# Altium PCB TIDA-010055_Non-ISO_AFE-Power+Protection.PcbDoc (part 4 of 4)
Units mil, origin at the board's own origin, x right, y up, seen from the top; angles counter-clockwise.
Board outline 3622.05 x 4330.71 mil, 4 copper layers (Top Layer, GND Layer, PWR Layer, Bottom Layer), stack 63.6 mil thick; 398 components, 177 nets, 1104 pads, 428 vias.
Unrouted connection lines stored in the file: 1.
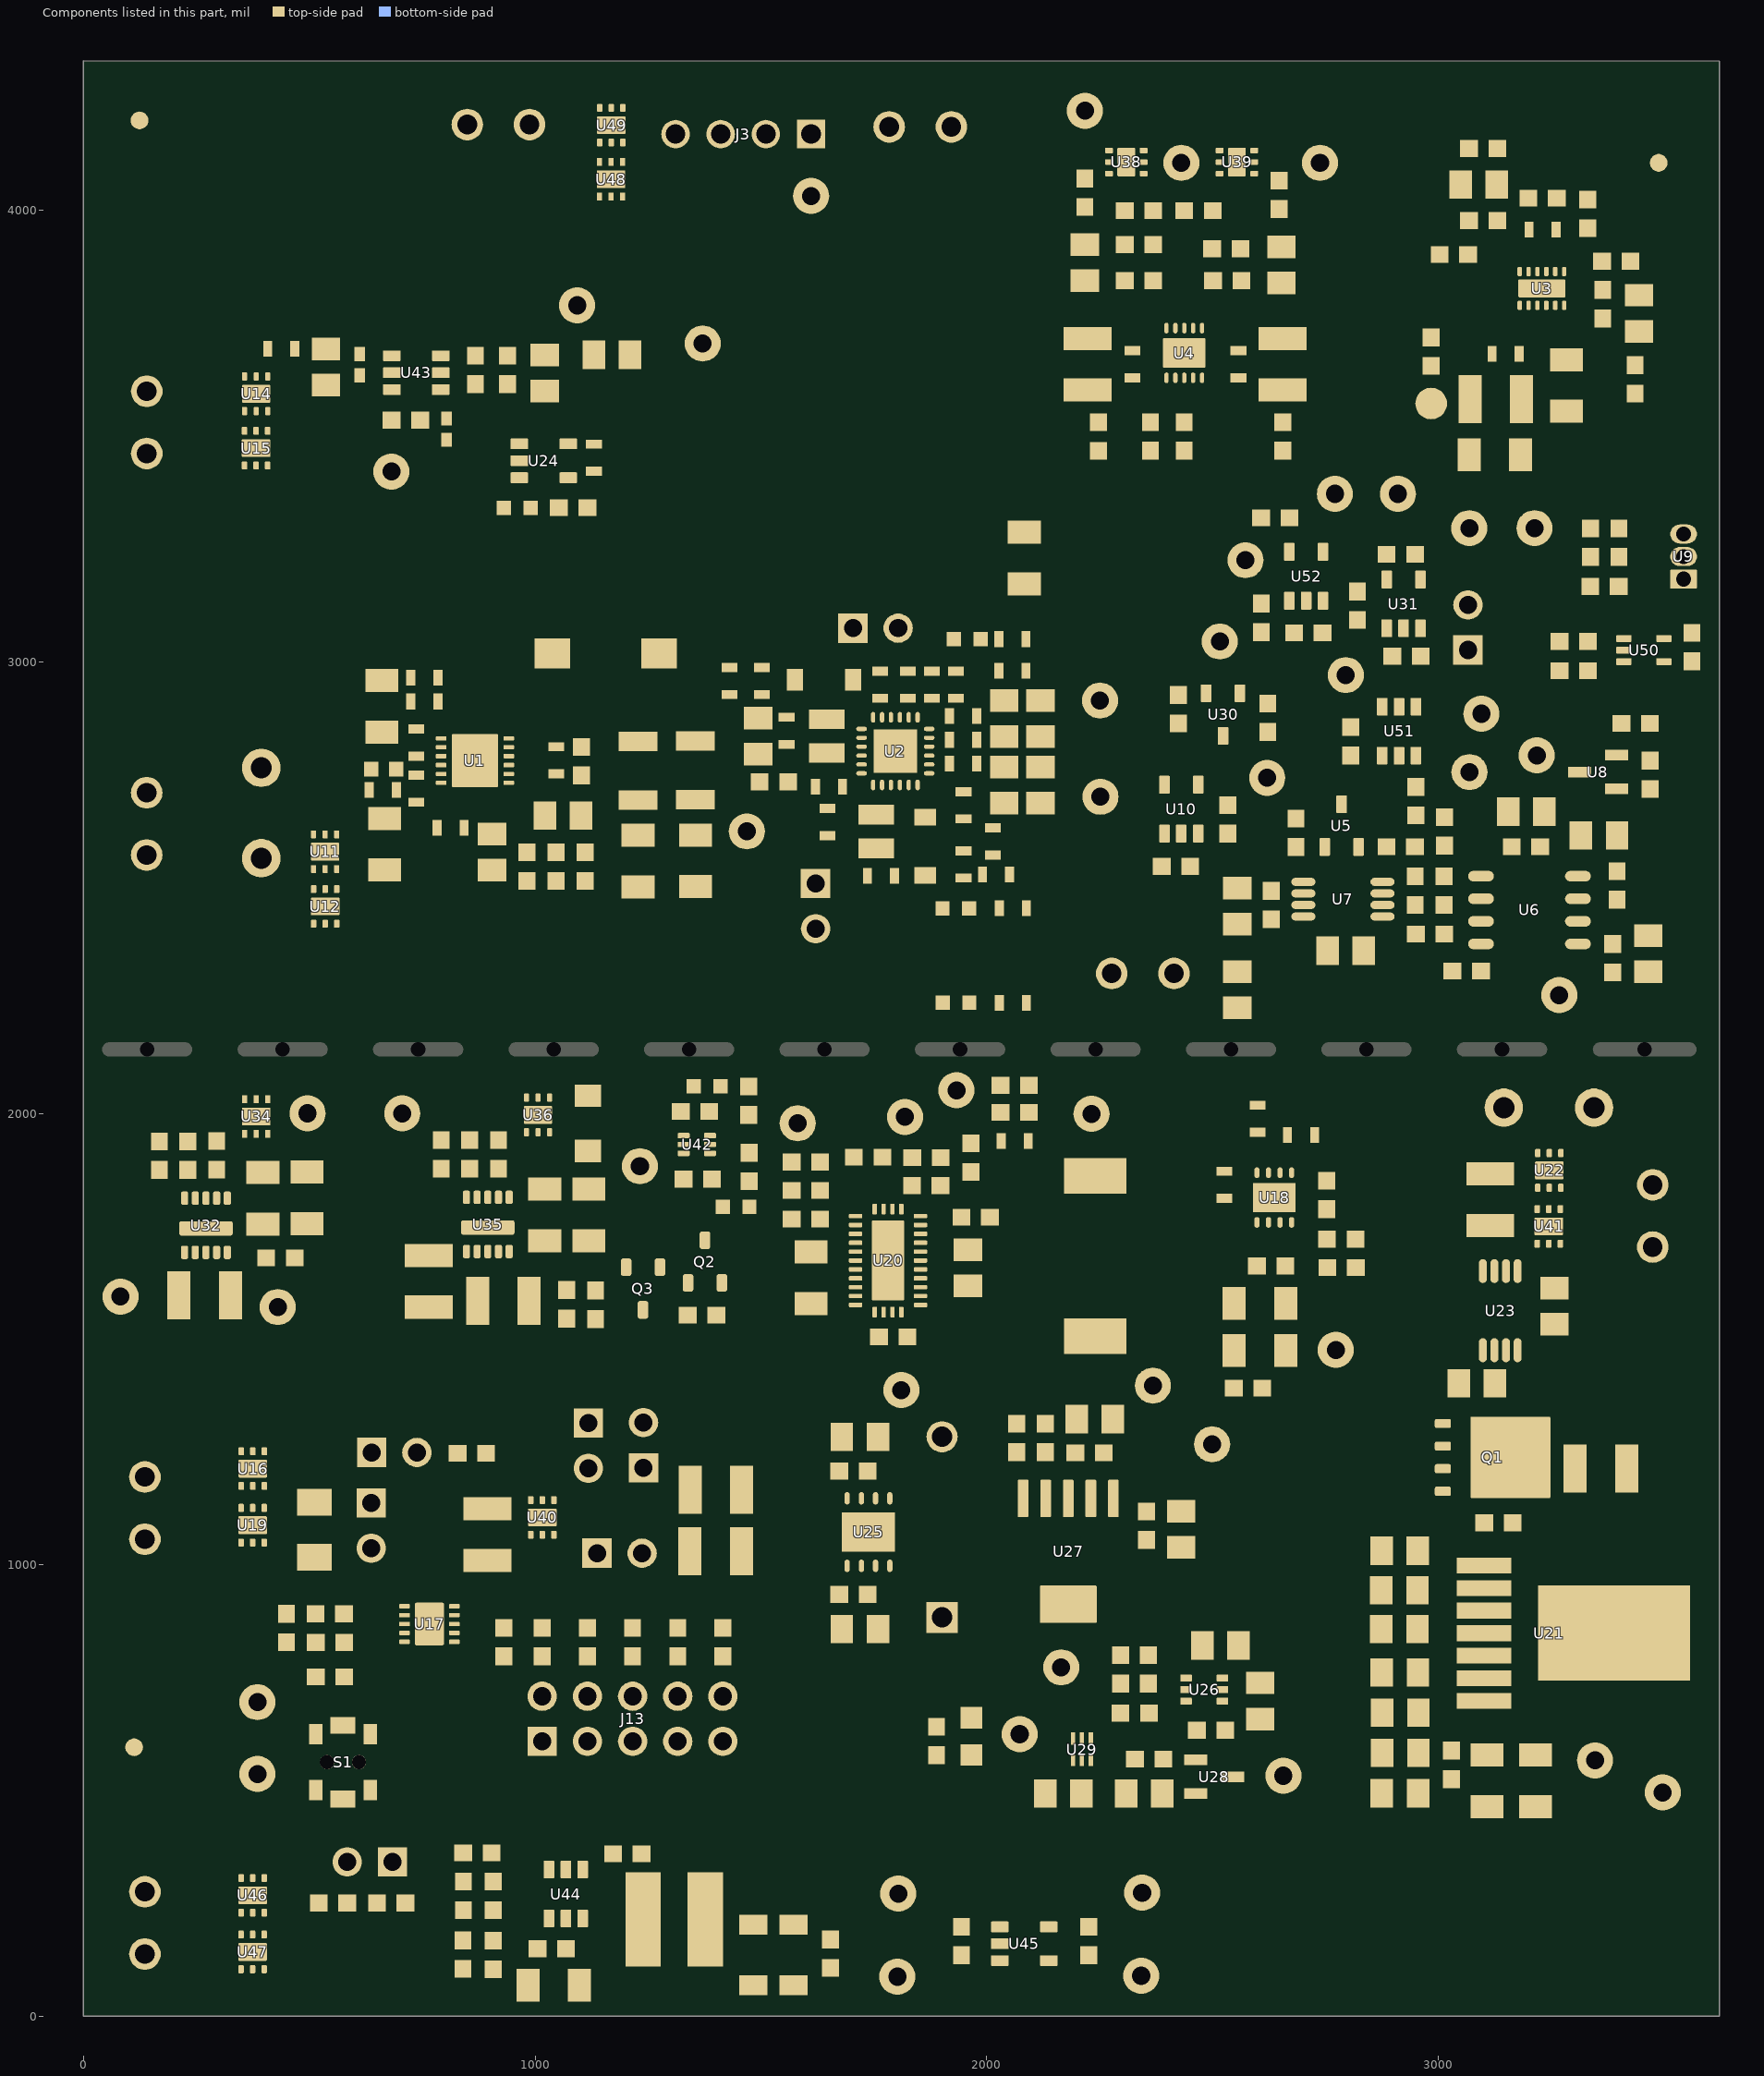
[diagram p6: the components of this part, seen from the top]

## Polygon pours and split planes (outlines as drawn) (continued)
NetU11_1 on Bottom Layer "Top Layer-No Net" (solid, pour order 84): 562.66,2588.76 504.66,2588.76 501.66,2585.76 501.66,2440.76 503.66,2438.76 564.66,2438.76 567.66,2441.76 567.66,2584.76 563.66,2588.76
NetU14_1 on Bottom Layer "Top Layer-No Net" (solid, pour order 90): 409.61,3603.56 351.61,3603.56 348.61,3600.56 348.61,3455.56 350.61,3453.56 411.61,3453.56 414.61,3456.56 414.61,3599.56 410.61,3603.56
NetJ4_1 on Bottom Layer "Top Layer-No Net" (solid, pour order 118): 127.88,2672.16 364.88,2672.16 434.88,2742.16 438.88,2746.16 438.88,2783.16 438.88,2786.16 413.88,2811.16 373.88,2811.16 354.88,2792.16 309.88,2747.16 140.88,2747.16 112.88,2747.16 100.88,2735.16 100.88,2686.16 114.88,2672.16
3.3V_1 on Bottom Layer "Top Layer-No Net" (solid, pour order 234): 23 vertices, not listed, extent 1677,1028 1939,1433
GND1 on Bottom Layer "Top Layer-No Net" (solid, pour order 252): 32 vertices, not listed, extent 38,1532 544,2047
24V/12V_IN on Bottom Layer "Top Layer-No Net" (solid, pour order 270): 3328.12,2084.89 3362.12,2084.89 3522.12,1924.89 3522.12,1839.89 3522.12,1824.89 3505.12,1807.89 3444.12,1807.89 3433.12,1818.89 3433.12,1883.89 3301.12,2015.89 3295.12,2021.89 3295.12,2051.89
-12V on Bottom Layer "net" (solid, remove dead copper, pour order 388): 2705,4161 2534,4161 2529,4156 2529,4054.67 2538.67,4045 2859.8,4045 3286,4045 3368,3963 3368,3526 3382,3512 3533,3512 3552,3531 3552,3626 3552,4018 3409,4161
+3.3V on Bottom Layer "net" (solid, remove dead copper, pour order 392): 2519,3009 2906,3396 3085,3396 3565,3396 3599,3362 3599,2251 3547,2199 3537.72,2189.72 2532.28,2189.72 2519,2203
NetC123_1 on Bottom Layer "vd" (solid, remove dead copper, pour order 534): 17 vertices, not listed, extent 437,31.57 1177.07,289
GND_S on Bottom Layer "net" (solid, remove dead copper, pour order 542): 73,388 3556,388 3577,367 3586,358 3590,354 3590,307 3590,53 3568,31 69,31 44,56 26,74 26,368 46,388
+5V_IN on Top Layer "vdd" (solid, remove dead copper, pour order 582): 1182,3824 1189,3831 1416,3831 1436,3811 1436,3651 1421,3636 1190,3636 1182,3644
EXT_5V on Top Layer "vdd" (solid, remove dead copper, pour order 580): 1061.26,3647.06 1051.32,3657 781.08,3657 768.28,3669.8 768.28,3816.28 782,3830 1148.89,3830 1156.89,3822 1156.89,3657.04 1146.92,3647.06
NetJ1_1 on Top Layer "vdd" (solid, remove dead copper, pour order 578): 436.52,3632 436.52,3724.48 429,3732 103.2,3732 77.49,3706.29 77.49,3581.4 95.64,3563.25 199.22,3563.25 258.97,3623 427.53,3623
GND on Top Layer "vdd" (solid, remove dead copper, pour order 576): 429.23,3441.58 272.5,3441.58 215.08,3499 91.49,3499 77.49,3485 77.49,3335.89 94.38,3319 458,3319 470,3331 470,3438 466,3442
GND on Top Layer "vdd" (solid, remove dead copper, pour order 572): 2273.09,3217.43 48.88,3217.43 -0.12,3168.43 -0.12,2268.43 77.31,2191 2284.11,2191 2310,2216.89 2310,3180.53
GND on Top Layer "Top Layer-No Net" (solid, pour order 570): 33 vertices, not listed, extent 103.01,2351.16 1505.88,3057.83
NetC1_1 on Top Layer "vdd" (solid, remove dead copper, pour order 568): 1182.88,3043.43 1195.88,3056.43 1345.88,3056.43 1360.88,3041.43 1360.88,2899.68 1410.41,2850.16 1410.41,2797.96 1398.88,2786.43 1192.2,2786.43 1182.88,2795.76
NetC2_2 on Top Layer "vdd" (solid, remove dead copper, pour order 562): 935.64,2799.72 927.88,2807.47 927.88,3045.83 939.88,3057.83 1119.78,3057.83 1131.88,3045.73 1131.88,2798.43 1123.88,2790.43 1076.17,2790.43 1066.88,2799.72
VIN on Top Layer "vd" (solid, remove dead copper, pour order 558): 20 vertices, not listed, extent 773,3947.71 1544.98,4260
AGND on Top Layer "vd" (solid, remove dead copper, pour order 556): 33 vertices, not listed, extent 947.98,4121.71 1978.98,4297.71
GND1 on Top Layer "vd" (solid, remove dead copper, pour order 518): 19 vertices, not listed, extent 896,1805 1271,1962.28
DCDC_-10P5V on Top Layer "vd" (solid, remove dead copper, pour order 516): 36 vertices, not listed, extent 662.09,1668.86 1161.09,2064.48
+24V_IN1 on Top Layer "vd" (solid, remove dead copper, pour order 510): 24 vertices, not listed, extent 266,1279 1156,1710
GND1 on Top Layer "vd" (solid, remove dead copper, pour order 506): 1019.75,1633.94 962.75,1633.94 952.75,1623.94 952.75,1490.94 958.75,1484.94 1020.75,1484.94 1026.75,1490.94 1026.75,1627.94 1020.75,1633.94
GND1 on Top Layer "net" (solid, remove dead copper, pour order 504): 36 vertices, not listed, extent 3000,430 3561,1768
VIN1 on Top Layer "net" (solid, remove dead copper, pour order 502): 22 vertices, not listed, extent 93.12,1103 683.12,1344
NetC127_2 on Top Layer "net" (solid, remove dead copper, pour order 484): 23 vertices, not listed, extent 1092.07,74.98 1283.07,381.98
GND_S on Top Layer "net" (solid, remove dead copper, pour order 482): 36 vertices, not listed, extent 67,31.6 1388,384
NetC123_1 on Top Layer "net" (solid, remove dead copper, pour order 478): 1058.07,184.98 1045.07,171.98 1045.07,38.57 1052.07,31.57 1173.67,31.57 1177.07,34.98 1177.07,166.98 1166.07,177.98 1088.07,177.98 1078.07,187.98 1078.07,238.41 1058.07,238.41
NetU46_1 on Top Layer "Top Layer-No Net" (solid, pour order 474): 401.9,281.42 343.9,281.42 340.9,278.42 340.9,133.42 342.9,131.42 403.9,131.42 406.9,134.42 406.9,277.42 402.9,281.42
NetC60_1 on Top Layer "net" (solid, remove dead copper, pour order 472): 459.99,3666.25 706.81,3666.25 711.81,3671.25 711.81,3718.25 703.81,3726.25 699.81,3730.25 558.81,3730.25 462.99,3730.25 454.99,3722.25 454.99,3671.25
NetC78_1 on Top Layer "net" (solid, remove dead copper, pour order 430): 43 vertices, not listed, extent 2892,1196 3287,2061
NetC79_1 on Top Layer "net" (solid, remove dead copper, pour order 424): 25 vertices, not listed, extent 3011,975 3325,1506
VDC_5V_1 on Top Layer "net" (solid, remove dead copper, pour order 410): 21 vertices, not listed, extent 1915,1741.35 2556.12,2091
-12V on Top Layer "net" (solid, remove dead copper, pour order 370): 2795,4055 2795,4150 2784,4161 2548,4161 2540,4153 2540,4054 2549,4045 2785,4045
+24V_IN on Top Layer "net" (solid, remove dead copper, pour order 368): 23 vertices, not listed, extent 1192,1281 1728,1790.89
NetC68_1 on Top Layer "net" (solid, remove dead copper, pour order 366): 17 vertices, not listed, extent 1201,967 1372,1235
GND1 on Top Layer "dg" (solid, remove dead copper, pour order 364): 783,1195 783,1106 793,1096 967,1096 980,1083 1049,1083 1061,1095 1061,1183 1043,1201 789,1201
VOUT1 on Top Layer "dg" (solid, remove dead copper, pour order 362): 30 vertices, not listed, extent 812,901 1276,1250
NetJ17_2 on Top Layer "dg" (solid, remove dead copper, pour order 358): 603,1063 603,963 627,939 665,901 705,901 711,901 711,1059 699,1071 611,1071
GND1 on Top Layer "dg" (solid, remove dead copper, pour order 354): 17 vertices, not listed, extent 93.12,821 566,1100.89
NetC75_2 on Top Layer "Top Layer-No Net" (solid, pour order 198): 18 vertices, not listed, extent 1836.12,1465 2377.12,1660.89
GND1 on Top Layer "Top Layer-No Net" (solid, pour order 172): 42 vertices, not listed, extent 1573.12,1500.89 2051.12,2091
NetC32_2 on Top Layer "Top Layer-No Net" (solid, pour order 66): 2282.4,3643.91 2268.4,3629.91 2258.4,3629.91 2160.4,3629.91 2156.4,3625.91 2156.4,3517.91 2164.4,3509.91 2268.4,3509.91 2292.4,3533.91 2375.4,3616.91 2375.4,3633.91 2375.4,3639.91 2371.4,3643.91
NetC36_1 on Top Layer "Top Layer-No Net" (solid, pour order 64): 22 vertices, not listed, extent 2167.4,3754.91 2367.4,4028.91
NetC40_2 on Top Layer "Top Layer-No Net" (solid, pour order 62): 2464.4,3945.91 2478.4,3959.91 2478.4,4008.91 2478.4,4017.91 2481.4,4020.91 2520.4,4020.91 2523.4,4017.91 2523.4,3824.91 2482.4,3783.91 2472.4,3783.91 2464.4,3791.91
NetC40_1 on Top Layer "Top Layer-No Net" (solid, pour order 60): 21 vertices, not listed, extent 2503.4,3763.91 2706.4,4023.91
AGND on Top Layer "Top Layer-No Net" (solid, pour order 58): 33 vertices, not listed, extent 2167.4,3654.47 2718.4,3868.91
NetC43_2 on Top Layer "Top Layer-No Net" (solid, pour order 56): 2592.4,3643.91 2606.4,3629.91 2616.4,3629.91 2714.4,3629.91 2718.4,3625.91 2718.4,3517.91 2710.4,3509.91 2606.4,3509.91 2582.4,3533.91 2499.4,3616.91 2499.4,3633.91 2499.4,3639.91 2503.4,3643.91
NetC36_2 on Top Layer "TOP_LAYER_NETC36_2_P050" (solid, remove dead copper, pour order 50): 2347.4,4009 2347.4,4014 2352.4,4019 2388.32,4019 2392.4,4014.91 2392.4,3975 2407.4,3960 2407.4,3769.47 cw(c2401.99,3778.65) 2402.4,3768 2397.4,3769 2347.4,3819
AGND on Top Layer "TOP_LAYER_AGND_P036" (solid, remove dead copper, pour order 36): 30 vertices, not listed, extent 3044.2,3525.5 3279.2,3936.98
NetU14_1 on Top Layer "Top Layer-No Net" (solid, pour order 30): 409.61,3603.56 351.61,3603.56 348.61,3600.56 348.61,3455.56 350.61,3453.56 411.61,3453.56 414.61,3456.56 414.61,3599.56 410.61,3603.56
NetU11_1 on Top Layer "Top Layer-No Net" (solid, pour order 26): 562.66,2588.76 504.66,2588.76 501.66,2585.76 501.66,2440.76 503.66,2438.76 564.66,2438.76 567.66,2441.76 567.66,2584.76 563.66,2588.76
NetC39_1 on Top Layer "Top Layer-No Net" (solid, pour order 68): 18 vertices, not listed, extent 3296.29,3637.23 3477.83,3795.23
NetC34_1 on Top Layer "Top Layer-No Net" (solid, pour order 70): 19 vertices, not listed, extent 3103.83,3891.23 3192.83,4161.23
NetC9_2 on Top Layer "Top Layer-No Net" (solid, pour order 72): 3155.83,3483.23 3155.83,3707.23 3172.83,3724.23 3194.83,3724.23 3206.83,3736.23 3214.83,3744.23 3214.83,3779.23 3214.83,3797.23 3224.83,3797.23 3224.83,3720.23 3211.83,3707.23 3211.83,3425.23 3206.83,3420.23 3160.83,3420.23 3155.83,3425.23
NetPT1_2 on Top Layer "Top Layer-No Net" (solid, pour order 74): 22 vertices, not listed, extent 342.88,2520.16 649.88,2734.16
NetJ4_1 on Top Layer "Top Layer-No Net" (solid, pour order 100): 127.88,2672.16 364.88,2672.16 434.88,2742.16 438.88,2746.16 438.88,2783.16 438.88,2786.16 413.88,2811.16 373.88,2811.16 354.88,2792.16 309.88,2747.16 140.88,2747.16 112.88,2747.16 100.88,2735.16 100.88,2686.16 114.88,2672.16
+3.3V on Top Layer "Top Layer-No Net" (solid, pour order 120): 19 vertices, not listed, extent 2455,2476.72 2764,2645.72
+5V_IN on Top Layer "Top Layer-No Net" (solid, pour order 140): 3093.98,3415.23 2990.98,3415.23 2984.98,3421.23 2984.98,3495.23 2989.98,3500.23 3092.98,3500.23 3097.98,3495.23 3097.98,3419.23
NetU16_1 on Top Layer "Top Layer-No Net" (solid, pour order 142): 402.04,1226.43 344.04,1226.43 341.04,1223.43 341.04,1078.43 343.04,1076.43 404.04,1076.43 407.04,1079.43 407.04,1222.43 403.04,1226.43
NetU22_1 on Top Layer "Top Layer-No Net" (solid, pour order 168): 3273.46,1890.75 3215.46,1890.75 3212.46,1887.75 3212.46,1742.75 3214.46,1740.75 3275.46,1740.75 3278.46,1743.75 3278.46,1886.75 3274.46,1890.75
NetC67_2 on Top Layer "g" (solid, remove dead copper, pour order 170): 39 vertices, not listed, extent 550.84,463.29 1545.84,1056.66
24V/12V_IN on Top Layer "Top Layer-No Net" (solid, pour order 200): 3328.12,2084.89 3362.12,2084.89 3522.12,1924.89 3522.12,1839.89 3522.12,1824.89 3505.12,1807.89 3444.12,1807.89 3433.12,1818.89 3433.12,1883.89 3301.12,2015.89 3295.12,2021.89 3295.12,2051.89
NetR65_1 on Top Layer "Top Layer-No Net" (solid, pour order 214): 2927.12,977.89 2979.12,977.89 2983.12,973.89 2983.12,824.89 2979.12,820.89 2931.12,820.89 2927.12,824.89
VDC_5V on Top Layer "Top Layer-No Net" (solid, pour order 218): 18 vertices, not listed, extent 2266,1097.1 2574,1626
GND1 on Top Layer "Top Layer-No Net" (solid, pour order 224): 30 vertices, not listed, extent 2051.6,871 2465,1401
3.3V_2 on Top Layer "Top Layer-No Net" (solid, pour order 226): 2414.12,1209 2257.89,1208.89 2248,1199 2248,1108.14 2240.03,1100.17 2219.83,1100.17 2212,1108 2212,1193 2240.03,1221.03 2240.03,1413.03 2270,1443 2411,1443 2418,1436 2418,1212.88
3.3V_1 on Top Layer "Top Layer-No Net" (solid, pour order 228): 23 vertices, not listed, extent 1677,1028 1939,1433
VDC_5V on Top Layer "Top Layer-No Net" (solid, pour order 232): 1714,1009 1714,914 1731,897 1731,819 1738,812 1932,812 1945,825 1945,915 1935,925 1858,925 1845,938 1845,1004 1836,1013 1718,1013
GND1 on Top Layer "Top Layer-No Net" (solid, pour order 236): 23 vertices, not listed, extent 1584,811 1706,1331
GND1 on Top Layer "Top Layer-No Net" (solid, pour order 238): 32 vertices, not listed, extent 38,1532 544,2047
DCDC_+10P5V on Top Layer "Top Layer-No Net" (solid, pour order 250): 28 vertices, not listed, extent 273,1797 544,2082
AGND on Top Layer "net" (solid, remove dead copper, pour order 380): 2290,4157 2299,4166 2503,4166 2524,4145 2524,4072.87 2501.13,4050 2307,4050 2290,4067
+12V on Top Layer "net" (solid, remove dead copper, pour order 382): 20 vertices, not listed, extent 2167.4,4050 3088,4277
+14V on Top Layer "net" (solid, remove dead copper, pour order 384): 2217,3489 2213,3485 2213,3417 2219,3411 2383,3411 2389,3417 2389,3486 2386,3489
GND1 on Top Layer "vd" (solid, remove dead copper, pour order 526): 29 vertices, not listed, extent 2588,1752 2785,1980.54
VDC_5V_2 on Top Layer "vd" (solid, remove dead copper, pour order 528): 17 vertices, not listed, extent 3004,523 3396,716
NetC123_1 on Top Layer "vd" (solid, remove dead copper, pour order 532): 20 vertices, not listed, extent 69,212 544,388
5V_S on Top Layer "vd" (solid, remove dead copper, pour order 536): 19 vertices, not listed, extent 1331.07,102.98 2051.55,348.98
GND_S on Top Layer "vd" (solid, remove dead copper, pour order 538): 19 vertices, not listed, extent 1415,31.6 2401,156
3V3_S on Top Layer "vd" (solid, remove dead copper, pour order 540): 2116,195 2116,335 2125,344 2392,344 2401,335 2401,198 2388,185 2381,178 2230,178 2119,178 2116,181
NetU48_1 on Top Layer "vd" (solid, remove dead copper, pour order 546): 1209.6,4054.71 1209.6,4193.09 1201.98,4200.71 1130.98,4200.71 1123.98,4193.71 1123.98,4055.71 1130.98,4048.71 1203.6,4048.71 1209.6,4054.71
+5V_IN on Top Layer "vd" (solid, remove dead copper, pour order 560): 21 vertices, not listed, extent 2418,2282 2636,2644.72
GND_S on GND Layer "net" (solid, remove dead copper, pour order 488): 73,388 3556,388 3577,367 3586,358 3590,354 3590,307 3590,53 3568,31 69,31 44,56 26,74 26,368 46,388
GND1 on GND Layer "Top Layer-No Net" (solid, remove dead copper, pour order 298): 834,2091 3555,2091 3591,2055 3591,446 3559,414 94,414 45,463 26,482 26,2061 53,2088 56,2091
GND on GND Layer "net" (solid, remove dead copper, pour order 454): 1182,2190.72 2284.94,2190.72 2310,2215.78 2310,3182 2275,3217 1495.92,3217 1453.92,3259 1453.92,3855.13 1411.05,3898 90.59,3898 26.51,3842 26.51,2210.21 46,2190.72
AGND on GND Layer "net" (solid, remove dead copper, pour order 456): 18 vertices, not listed, extent 27.35,2189.72 3599,4303
+5V_IN on PWR Layer "vd" (solid, remove dead copper, pour order 530): 46,2190.72 26.51,2210.21 26.51,4229.51 101,4304 103,4302 3550,4302 3599,4253 3599,2251 3537.72,2189.72 3536.72,2190.72
NetC123_1 on PWR Layer "net" (solid, remove dead copper, pour order 498): 73,388 3556,388 3577,367 3586,358 3590,354 3590,307 3590,53 3568,31 69,31 44,56 26,74 26,368 46,388
VIN1 on PWR Layer "Top Layer-No Net" (solid, remove dead copper, pour order 436): 834,2091 3555,2091 3591,2055 3591,446 3559,414 94,414 45,463 26,482 26,2061 53,2088 56,2091
GND on M4 3D STEP Bottom "net" (solid, remove dead copper, pour order 438): 26.51,2210.21 26.51,4229.51 81,4284 101,4304 1096,4304 1115,4285 1115,3572.72 1115,2984.72 1182,2917.72 1182,2190.72 46,2190.72
no net on M4 3D STEP Bottom "net" (solid, remove dead copper, pour order 450): 1257,2217.72 1257,2896.72 1342,2981.72 1342,3574 1342,4264 1380,4302 2293,4302 2310,4285 2310,2883.72 2310,2212.72 2288,2190.72 1284,2190.72

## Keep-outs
Keep-Out Layer:
  the board outline again, w10
  text ".Layer_Name" at 179.39,-1385.08 h60

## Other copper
Top Layer:
  text ".Layer_Name" at 179.39,-1385.08 h60
GND Layer:
  text ".Layer_Name" at 198,-1378 h40
PWR Layer:
  text ".Layer_Name" at 211,-1380 h40
Bottom Layer:
  text ".Layer_Name" at 179.39,-1385.08 h60

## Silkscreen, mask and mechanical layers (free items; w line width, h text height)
Top Overlay:
  circle w6: c2199.88,2805.65 r31.85
  circle w6: c1736.88,3442 r31.85
  lines w6: 759,2867.77 774.61,2883.38 846.1,2883.38 854.65,2891.93 ; 2188,2840.16 2188,2943 2176.02,2954.98 1983.02,2954.98 1983.02,2903.71 1898.6,2903.71 1898.6,2736.4 1981.49,2736.4 1981.49,2648.49 2189.51,2648.49 2189.51,2772.51 ; 1692,3232 1896.88,3232 1896.88,3490.88 1722.88,3490.88 1692,3460 1692,3438.87 1692,3232
  lines w10: 601.88,2490.43 601.88,2563.43
  text "+12V" at 2176,4286 h25
  text "-12V" at 2688,4212 h25
  text ".PRJ_Number" at 444,3878 h40
  text "A" at 1722,3423 h40
  text "+14V" at 2200,3024 h25
  text "A" at 2185,2786.65 h40
  text "-14V" at 2204,2574 h25
  text "GND1" at 44,1507 h25
  text "+24V_IN1" at 376.09,1479.8 h25
  text "5V_S" at 1764,342 h25
  text ".Layer_Name" at 179.39,-1385.08 h60
Bottom Overlay:
  text ".Layer_Name" at 179.39,-1385.08 h60
Top Paste:
  text ".Layer_Name" at 179.39,-1385.08 h60
Bottom Paste:
  text ".Layer_Name" at 179.39,-1385.08 h60
Top Solder:
  text ".Layer_Name" at 179.39,-1385.08 h60
  text ".Layer_Name" at 179.39,-1385.08 h60
Bottom Solder:
  text ".Layer_Name" at 179.39,-1385.08 h60
Drill Guide:
  text ".Layer_Name" at 179.39,-1385.08 h60
M1 Board Outline:
  the board outline again, w10
M2 Board Dimensions:
  rectangle: -272.61,-926.58 102.39,-801.58
  rectangle: -397.61,-801.58 -272.61,-676.58
  lines w7: -397.61,-801.58 602.39,-801.58 ; -272.61,-926.58 -272.61,-676.58 ; -147.61,-926.58 -147.61,-676.58 ; 102.39,-926.58 102.39,-676.58 ; 352.39,-926.58 352.39,-676.58 ; -397.61,-926.58 -397.61,-676.58 602.39,-676.58 602.39,-926.58 -397.61,-926.58
M3 3D STEP Top:
  text ".Layer_Name" at 179.39,-1385.08 h60
M4 3D STEP Bottom:
  text ".Layer_Name" at 179.39,-1385.08 h60
M5 Assembly Top:
  circle w10: c2670.25,3119 r5.39
  circle w6: c3394.68,3052 r6.32
  circle w6: c1338.68,1612 r6.32
  circle w6: c1277,1675 r6.32
  circle w10: c2008.07,198.98 r8.54
  circle w10: c2280,1030 r11.18
  circle w10: c946.6,3483.2 r5.39
  circle w10: c2886,3059 r5.39
  circle w10: c3543,3183 r5.39
  circle w10: c2561.25,2948 r5.39
  circle w10: c3389.8,2718.32 r5.39
  circle w10: c2746.61,2629 r5.39
  circle w10: c2390.61,2659 r5.39
  circle w10: c2491,568.04 r5.39
  circle w10: c1616.35,4257.71 r12.37
  lines w6: 3326.29,2814 3432,2814 3432,2697 3326.62,2697 3326.62,2814.45 3326.29,2814.78
  lines w10: -689.61,-1456.75 5910.39,-1456.75 ; -689.61,-1253.42 5912.39,-1253.42 ; -689.61,-1050.08 -689.61,-1660.08 3315.39,-1660.08 5912.39,-1660.08 5912.39,-1050.08 -689.11,-1050.08 -689.11,-1660.08 886.39,-1660.08 ; 1775.39,-1660.08 1775.39,-1050.08 ; 3042.39,-1253.42 3042.39,-1050.08 ; 3882.39,-1253.42 3882.39,-1050.08 ; 4504.39,-1666.58 4504.39,-1463.75
  text "COMPONENTS MARKED 'DNP' SHOULD NOT BE POPULATED." at 755.89,-845.08 h20
  text "ASSEMBLY VARIANT:" at 755.39,-960.58 h20
  text ".VariantName" at 1791.39,-960.58 h20
  text "PCB VIEWED FROM TOP SIDE" at -626.11,-1182.25 h20
  text "BOARD #:" at 1850.39,-1182.25 h20
  text ".PRJ_Number" at 2395.89,-1182.25 h20
  text "REV:" at 3240.39,-1182.25 h20
  text ".PCB_Rev" at 3531.89,-1182.25 h20
  text "SVN REV:" at 4078.39,-1182.25 h20
  text ".VersionControl_RevNumber" at 4584.39,-1182.25 h20
  text ".Layer_Name" at 181,-1380 h20
  text "LAYER NAME =" at -626.11,-1385.08 h20
  text "TID #:" at 1850.39,-1385.58 h20
  text ".TID" at 2395.89,-1385.58 h20
  text "PLOT NAME =" at -626.11,-1590.92 h20
  text ".plot_File_Name" at 179.39,-1590.92 h20
  text "GENERATED    :" at 1852.39,-1590.92 h20
  text ".Print_Date" at 2721.89,-1590.92 h20
  text ".Print_Time" at 3450.89,-1590.92 h20
  text "TEXAS INSTRUMENTS" at 4715.39,-1590.92 h20
M6 Assembly Bottom:
  lines w10: -690.11,-1253.92 5911.89,-1253.92 ; -688.11,-1457.25 5911.89,-1457.25 ; 717.89,-1667.08 717.89,-1464.25 ; 1339.89,-1253.92 1339.89,-1050.58 ; 2179.89,-1253.92 2179.89,-1050.58 ; 3446.89,-1660.58 3446.89,-1050.58 ; 4335.89,-1660.58 5911.39,-1660.58 5911.39,-1050.58 -690.11,-1050.58 -690.11,-1660.58 1906.89,-1660.58 5911.89,-1660.58 5911.89,-1050.58
  text "COMPONENTS MARKED 'DNP' SHOULD NOT BE POPULATED." at 5704.39,-844.58 h20
  text ".VariantName" at 4660.39,-960.58 h20
  text "ASSEMBLY VARIANT:" at 5699.39,-960.58 h20
  text ".VersionControl_RevNumber" at 637.89,-1182.75 h20
  text "SVN REV:" at 1143.89,-1182.75 h20
  text ".PCB_Rev" at 1690.39,-1182.75 h20
  text "REV:" at 1981.89,-1182.75 h20
  text ".PRJ_Number" at 2826.39,-1182.75 h20
  text "BOARD #:" at 3371.89,-1182.75 h20
  text "PCB VIEWED FROM BOTTOM SIDE" at 5848.39,-1182.75 h20
  text ".TID" at 2826.39,-1386.08 h20
  text "TID #:" at 3371.89,-1386.08 h20
  text "TEXAS INSTRUMENTS" at 506.89,-1591.42 h20
  text ".Print_Time" at 1771.39,-1591.42 h20
  text ".Print_Date" at 2500.39,-1591.42 h20
  text "GENERATED    :" at 3369.89,-1591.42 h20
  text ".plot_File_Name" at 5042.89,-1591.42 h20
  text "PLOT NAME =" at 5848.39,-1591.42 h20
M9 Title Sheet:
  drawing of 57 lines, arcs and shapes, not listed
  text "1" at 342.22,7509.92 h70
  text "2" at 2837.89,7509.92 h70
  text "3" at 5327.23,7509.92 h70
  text "4" at 7833.9,7509.92 h70
  text "5" at 10332.89,7509.92 h70
  text "6" at 12837.89,7509.92 h70
  text "A" at -814.11,6366.92 h70
  text "A" at 13985.89,6366.92 h70
  text "A" at 13987.91,6366.14 h70
  text "B" at -814.11,3986.92 h70
  text "B" at 13985.89,3986.92 h70
  text "B" at 13987.91,3986.14 h70
  text "C" at -814.11,1611.92 h70
  text "C" at 13985.89,1611.92 h70
  text "C" at 13987.91,1611.14 h70
  text "PROJECT TITLE:" at 10945.89,-249.08 h45
  text ".PRJ_Title" at 10995.89,-382.41 h70
  text "DESIGNED FOR:" at 10945.89,-550.08 h45
  text ".PRJ_Customer" at 10995.89,-690.08 h70
  text "D" at -814.11,-758.08 h70
  text "D" at 13985.89,-758.08 h70
  text "FILE NAME:" at 10945.89,-850.08 h45
  text ".PCB_File_Name_No_Path" at 10995.89,-970.08 h70
  text "Texas Instruments (TI) and/or its licensors do not warrant the accuracy or completeness of this specification" at 5976.39,-1131.92 h45
  text "ENGINEER:" at 10945.89,-1140.08 h45
  text "LAYOUT BY:" at 12450.89,-1140.08 h45
  text "or any information contained therein. TI and/or its licensors do not warrant that this design will meet" at 5931.4,-1244.59 h45
  text ".PRJ_Engineer" at 10995.89,-1295.08 h70
  text ".PCB_Layout" at 12501.39,-1295.08 h70
  text "the specifications, will be suitable for your application or fit for any particular purpose, or will operate in" at 5931.4,-1357.25 h45
  text "ALTIUM DESIGNER VERSION:" at 12450.89,-1450.08 h45
  text "an implementation. TI and/or its licensors do not warrant that the design is production worthy. You should" at 5931.4,-1469.92 h45
  text "completely validate and test your design implementation to confirm the system functionality for your application." at 5976.39,-1582.58 h45
  text ".print_Scale" at 10995.89,-1583.41 h70
  text ".Application_BuildNumber" at 12501.39,-1583.41 h70
  text "1" at 342.22,-1790.08 h70
  text "2" at 2837.89,-1790.08 h70
  text "3" at 5327.23,-1790.08 h70
  text "4" at 7833.9,-1790.08 h70
  text "5" at 10332.89,-1790.08 h70
  text "6" at 12837.89,-1790.08 h70
M10 Fab Notes:
  drawing of 227 lines, arcs and shapes, not listed
  text "DESIGN INFORMATION" at 11973.86,6273.36 h60
  text "(REFER ALSO ARRAY/PANEL PROFILING INFORMATION)" at 11622.35,6107.29 h60
  text "BOARD SIZE" at 10936.35,6103 h60
  text "92MM" at 11412.37,5988.64 h60
  text "X" at 11904.35,5975.18 h60
  text "110MM" at 12111,5974 h60
  text "Number of Layers :" at 11339.34,5778 h60
  text "4" at 12411.89,5773 h60
  text "8" at 12412.82,5641.2 h60
  text "MIN. TRACK WIDTH:" at 11339.34,5639 h60
  text "MIL" at 12590.34,5639 h60
  text "MIN. CLEARANCE:" at 11339.34,5507 h60
  text "8" at 12433.37,5507.64 h60
  text "MIL" at 12590.34,5507 h60
  text "MIN. VIA DRILL SIZE:" at 11339.34,5375 h60
  text "7.874" at 12277.82,5375.2 h60
  text "MIL" at 12590.34,5375 h60
  text "6 MIL ( 0.1524 mm)" at 12034.35,5233.29 h60
  text "MINIMUM ANNULAR RING" at 11010.11,5229 h60
  text "EXTERNAL" at 12925.89,5218 h60
  text "PER" at 11210.11,5111 h60
  text "IPC-D-275 CLASS 2 LEVEL C" at 11430.11,5111 h60
  text "+/-" at 12525.89,4998 h60
  text "MIL, HOLES" at 12918.34,4998.71 h60
  text "+/-" at 13379.89,4998 h60
  text "REGISTRATION TOLERANCES:" at 11010.11,4993 h60
  text "METAL" at 12209.89,4993 h60
  text "5" at 12786.09,4993 h60
  text "3" at 13619.09,4993 h60
  text "MIL" at 13735.34,4993 h60
  text "MATERIAL:" at 10935.35,4783.54 h60
  text "FR-4 High Tg" at 11921.79,4643.21 h60
  text "X" at 11762.89,4635 h60
  text "FR-408" at 11356.35,4634.64 h60
  text "OTHER" at 12844.35,4634.64 h60
  text "63 MIL (1.6mm) +/-10%" at 11676.45,4471.92 h60
  text "THICKNESS:" at 11010.11,4467.64 h60
  text "X" at 11548.28,4467.64 h60
  text "OTHER" at 12961.35,4467.64 h60
  text "TOLERANCE:" at 11010.11,4309.64 h60
  text "X" at 11849.42,4309.64 h60
  text "ANSI IPC-6012 TYPE 3 CLASS 2" at 12036.36,4309.64 h60
  text "OTHER +/-" at 12036.35,4153.64 h60
  text "BOW & TWIST:" at 11010.11,3996.64 h60
  text "X" at 11849.42,3996.64 h60
  text "ANSI IPC-6012 TYPE 3 CLASS 2" at 12036.36,3996.64 h60
  text "OTHER +/-" at 12036.35,3838.13 h60
  text "COPPER THICKNESS (FINISHED):" at 10935.35,3702.64 h60
  text "1.4MIL (1oz)" at 11815.34,3549.92 h60
  text "2MIL (1.4oz)" at 12582.35,3549.92 h60
  text "2.8MIL (2oz)" at 13309.35,3549.92 h60
  text "OUTER:" at 11292.35,3545.64 h60
  text "X" at 11686.89,3545 h60
  text "X" at 11682.89,3395 h60
  text "1.4MIL (1oz)" at 11815.34,3392.92 h60
  text "2.8MIL (2oz)" at 12582.35,3392.92 h60
  text "N/A" at 13308.89,3393.29 h60
  text "INNER SIGNAL:" at 11003.26,3388.64 h60
  text "DRILLING:" at 10935.35,3249.64 h60
  text "REFERENCE:" at 11010.11,3132.64 h60
  text "X" at 11658.35,3132.64 h60
  text "AS SHOWN" at 11845.34,3132.64 h60
  text "X" at 12559.35,3132.64 h60
  text "NC_DRILL FILES" at 12696.34,3132.64 h60
  text "PTH MIN COPPER THICKNESS:" at 11010.11,2974.64 h60
  text "X" at 12360.35,2974.64 h60
  text "1MIL" at 12497.34,2974.64 h60
  text "OTHER" at 12994.35,2974.64 h60
  text "BOARD FINISH:" at 10935.35,2815.64 h60
  text "SILKSCREEN:" at 11090.57,2697.64 h60
  text "X" at 12039.35,2697.64 h60
  text "TOP" at 12165.34,2697.64 h60
  text "X" at 12549.35,2697.64 h60
  text "BOTTOM" at 12676.34,2697.64 h60
  text "SILKSCREEN COLOR:" at 11090.57,2530.64 h60
  text "X" at 12038.3,2530.64 h60
  text "WHITE" at 12165.34,2530.64 h60
  text "OTHER" at 12676.34,2530.64 h60
  text "SOLDER RESIST COLOR:" at 11090.57,2360.64 h60
  text "X" at 11658.31,2201.44 h60
  text "GREEN" at 11785.34,2201.44 h60
  text "BLUE" at 12376.34,2201.44 h60
  text "OTHER" at 12914.35,2201.44 h60
  text "IMMERSION GOLD (ENIG)" at 11996.34,2012.92 h60
  text "ENEPIG" at 13333.89,2009.64 h60
  text "SURFACE FINISH:" at 10935.35,2008.64 h60
  text "X" at 11809.4,2008.64 h60
  text "IMM. TIN/SILVER OR EQUIV" at 11264.89,1851.64 h60
  text "OTHER" at 12696.35,1851.64 h60
  text "ARRAY/PANEL:" at 10935.35,1672.64 h60
  text "CUT AND TRIM PER MECH LAYER 1" at 11996.35,1668.35 h60
  text "N.C. ROUTE" at 11996.34,1516.64 h60
  text "X" at 12675.35,1516.64 h60
  text "V. SCORE" at 12862.35,1516.64 h60
  text "CERTIFICATION:" at 10935.35,1379.64 h60
  text "MATERIALS AND WORKMANSHIP FOR ALL PCBS" at 11660.35,1379.64 h60
  text "TO MEET OR EXCEED THE REQUIREMENTS OF:" at 11660.35,1281.64 h60
  text "X" at 11286.85,1145.13 h60
  text "ANSI IPC-A-600F CLASS ->" at 11425.85,1145.13 h60
  text "X" at 13064.9,1145.13 h60
  text "2" at 13183.85,1145.14 h60
  text "1" at 12868.85,1143.64 h60
  text "3" at 13537.85,1143.64 h60
  text "X" at 11288.9,985.64 h60
  text "UL 94V-0" at 11425.85,985.64 h60
  text "X" at 12100.9,985.64 h60
  text "RoHS" at 12237.85,985.64 h60
  text "OTHER" at 12882.25,985.64 h60
  text "PER ORDER" at 13279.31,985.64 h60
  text "VIA TENTING:" at 12152.89,852 h60
  text "X" at 12915.37,848.64 h60
  text "ADDITIONAL REQUIREMENTS:" at 10935.35,844.64 h60
  text "YES" at 12702.55,842.92 h60
  text "NO" at 13067.36,837.69 h60
  text "MICROSECTION:" at 11010.11,729.64 h60
  text "YES" at 11915.85,729.64 h60
  text "IMPEDANCE CONTROL:" at 12174.89,723 h60
  text "YES" at 13158.89,722 h60
  text "X" at 13700.89,715 h60
  text "NO" at 13534.36,704.69 h60
  text "REQUIRED" at 12777.34,573.49 h60
  text "BARE BOARD ELEC. TEST:" at 11010.11,570.64 h60
  text "NONE" at 12315.85,570.64 h60
  text "X" at 12650.35,570.64 h60
  text "PER ORDER" at 13369.35,570.64 h60
  text "MANUFACTURER'S UL:" at 11010.11,413.64 h60
  text "RAIL" at 12175.85,409.35 h60
  text "METAL" at 12667.66,409.35 h60
  text "X" at 13042.89,409 h60
  text "SILK" at 13179.34,409.35 h60
M11 Gerber Information:
  lines w10: -689.61,-1456.75 5910.39,-1456.75 ; -689.61,-1253.42 5912.39,-1253.42 ; -689.61,-1050.08 -689.61,-1660.08 3315.39,-1660.08 5912.39,-1660.08 5912.39,-1050.08 -689.11,-1050.08 -689.11,-1660.08 886.39,-1660.08 ; 1775.39,-1660.08 1775.39,-1050.08 ; 3042.39,-1253.42 3042.39,-1050.08 ; 3882.39,-1253.42 3882.39,-1050.08 ; 4504.39,-1666.58 4504.39,-1463.75
  text ".PRJ_Number" at 2307,-1172 h30
  text "ALL ARTWORK VIEWED FROM TOP SIDE" at -626.11,-1182.25 h60
  text "BOARD #:" at 1850.39,-1182.25 h60
  text "REV:" at 3240.39,-1182.25 h60
  text ".PCB_Rev" at 3531.89,-1182.25 h60
  text "SVN REV:" at 4078.39,-1182.25 h60
  text ".VersionControl_RevNumber" at 4584.39,-1182.25 h60
  text "LAYER NAME =" at -626.11,-1385.08 h60
  text "TID #:" at 1850.39,-1385.58 h60
  text ".TID" at 2395.89,-1385.58 h60
  text "PLOT NAME =" at -626.11,-1590.92 h60
  text ".plot_File_Name" at 179.39,-1590.92 h30
  text "GENERATED    :" at 1852.39,-1590.92 h60
  text ".Print_Date" at 2721.89,-1590.92 h60
  text ".Print_Time" at 3450.89,-1590.92 h60
  text "TEXAS INSTRUMENTS" at 4715.39,-1590.92 h60
M12 Stackup:
  drawing of 295 lines, arcs and shapes, not listed
  text "Layer" at 4090.5,6281.5 h60
  text "Name" at 4500.41,6281.5 h60
  text "Material" at 5430.16,6281.5 h60
  text "Thickness" at 6289.92,6281.5 h60
  text "Constant" at 6939.76,6281.5 h60
  text "Board Layer Stack" at 7509.62,6281.5 h60
  text "1" at 4090.5,6161.5 h60
  text "Top Overlay" at 4500.41,6161.5 h60
  text "2" at 4090.5,6041.5 h60
  text "Top Solder" at 4500.41,6041.5 h60
  text "Solder Resist" at 5430.16,6041.5 h60
  text "0.30mil" at 6289.92,6041.5 h60
  text "3.5" at 6939.76,6041.5 h60
  text "3" at 4090.5,5921.5 h60
  text "Top Layer" at 4500.41,5921.5 h60
  text "Copper" at 5430.16,5921.5 h60
  text "1.40mil" at 6289.92,5921.5 h60
  text "4" at 4090.5,5801.5 h60
  text "Dielectric1" at 4500.41,5801.5 h60
  text "FR-4 High Tg" at 5430.16,5801.5 h60
  text "15.00mil" at 6289.92,5801.5 h60
  text "4.5" at 6939.76,5801.5 h60
  text "5" at 4090.5,5681.5 h60
  text "GND Layer" at 4500.41,5681.5 h60
  text "Copper" at 5430.16,5681.5 h60
  text "1.40mil" at 6289.92,5681.5 h60
  text "6" at 4090.5,5561.5 h60
  text "Dielectric 2" at 4500.41,5561.5 h60
  text "FR-4 High Tg" at 5430.16,5561.5 h60
  text "28.00mil" at 6289.92,5561.5 h60
  text "4.5" at 6939.76,5561.5 h60
  text "7" at 4090.5,5441.5 h60
  text "PWR Layer" at 4500.41,5441.5 h60
  text "Copper" at 5430.16,5441.5 h60
  text "1.40mil" at 6289.92,5441.5 h60
  text "8" at 4090.5,5321.5 h60
  text "Dielectric 3" at 4500.41,5321.5 h60
  text "FR-4 High Tg" at 5430.16,5321.5 h60
  text "15.00mil" at 6289.92,5321.5 h60
  text "4.5" at 6939.76,5321.5 h60
  text "9" at 4090.5,5201.5 h60
  text "Bottom Layer" at 4500.41,5201.5 h60
  text "Copper" at 5430.16,5201.5 h60
  text "1.40mil" at 6289.92,5201.5 h60
  text "10" at 4090.5,5081.5 h60
  text "Bottom Solder" at 4500.41,5081.5 h60
  text "Solder Resist" at 5430.16,5081.5 h60
  text "0.30mil" at 6289.92,5081.5 h60
  text "3.5" at 6939.76,5081.5 h60
  text "11" at 4090.5,4961.5 h60
  text "Bottom Overlay" at 4500.41,4961.5 h60
M13 Component Bodies Top:
  text ".Layer_Name" at 179.39,-1385.08 h60
M14 Component Bodies Bottom:
  text ".Layer_Name" at 179.39,-1385.08 h60
M15 Courtyards Top:
  text ".Layer_Name" at 179.39,-1385.08 h60
M16 Courtyards Bottom:
  text ".Layer_Name" at 179.39,-1385.08 h60
Drill Drawing:
  circle w10: c3879.62,2318.27 r20
  circle w10: c3879.62,2318.27 r33.33
  circle w10: c3879.62,1718.28 r33.33
  lines w10: 3846.29,1984.94 3912.96,1984.94 3912.96,2051.61 3846.29,2051.61 3846.29,1984.94 ; 3846.29,2168.27 3879.62,2134.94 3912.96,2168.27 3879.62,2201.61 3846.29,2168.27 ; 3846.29,2801.61 3912.96,2801.61 3879.62,2734.94 3846.29,2801.61 ; 3846.29,2884.94 3846.29,2901.61 3862.96,2918.27 3846.29,2934.94 3846.29,2951.61 3862.96,2951.61 3879.62,2934.94 3896.29,2951.61 3912.96,2951.61 3912.96,2934.94 3896.29,2918.27 3912.96,2901.61 3912.96,2884.94 3896.29,2884.94 3879.62,2901.61 3862.96,2884.94 3846.29,2884.94 ; 3846.29,3051.61 3862.96,3051.61 3862.96,3034.94 3896.29,3034.94 3896.29,3051.61 3912.96,3051.61 3912.96,3084.94 3896.29,3084.94 3896.29,3101.61 3862.96,3101.61 3862.96,3084.94 3846.29,3084.94 3846.29,3051.61 ; 3846.29,3184.94 3879.62,3201.61 3912.96,3184.94 3896.29,3218.27 3912.96,3251.61 3879.62,3234.94 3846.29,3251.61 3862.96,3218.27 3846.29,3184.94 ; 3846.29,3334.94 3912.96,3334.94 3912.96,3401.61 3846.29,3401.61 3846.29,3334.94 ; 3846.29,3501.61 3862.96,3501.61 3862.96,3484.94 3896.29,3484.94 3896.29,3501.61 3912.96,3501.61 3912.96,3534.94 3896.29,3534.94 3896.29,3551.61 3862.96,3551.61 3862.96,3534.94 3846.29,3534.94 3846.29,3501.61 ; 3846.29,3701.61 3912.96,3701.61 3879.62,3634.94 3846.29,3701.61 ; 3859.62,2788.27 3899.62,2788.27 3879.62,2748.27 3859.62,2788.27 ; 3859.62,3058.27 3869.62,3058.27 3869.62,3048.27 3889.62,3048.27 3889.62,3058.27 3899.62,3058.27 3899.62,3078.27 3889.62,3078.27 3889.62,3088.27 3869.62,3088.27 3869.62,3078.27 3859.62,3078.27 3859.62,3058.27 ; 3859.62,3348.27 3899.62,3348.27 3899.62,3388.27 3859.62,3388.27 3859.62,3348.27
  lines w15: 3786.5,1639.94 8481.24,1639.94 ; 3786.5,3739.94 8481.24,3739.94 ; 4337.38,1489.94 4337.38,3889.94 ; 4937.22,1489.94 4937.22,3889.94 ; 6036.9,1489.94 6036.9,3889.94 ; 6542.77,1489.94 6542.77,3889.94 ; 7276.57,1489.94 7276.57,3889.94 ; 3786.5,1489.94 8481.24,1489.94 8481.24,3889.94 3786.5,3889.94 3786.5,1489.94
  text "Symbol" at 3876.5,3784.94 h72
  text "Count" at 4382.38,3784.94 h72
  text "Hole Size" at 4982.22,3784.94 h72
  text "Plated" at 6081.9,3784.94 h72
  text "Hole Type" at 6587.77,3784.94 h72
  text "Hole Length" at 7321.57,3784.94 h72
  text "78" at 4382.38,3634.94 h60
  text "7.87mil (0.200mm)" at 4982.22,3634.94 h60
  text "PTH" at 6081.9,3634.94 h60
  text "Round" at 6587.77,3634.94 h60
  text "-" at 7321.57,3634.94 h60
  text "11" at 4382.38,3484.94 h60
  text "8.00mil (0.203mm)" at 4982.22,3484.94 h60
  text "PTH" at 6081.9,3484.94 h60
  text "Round" at 6587.77,3484.94 h60
  text "-" at 7321.57,3484.94 h60
  text "2" at 4382.38,3334.94 h60
  text "10.00mil (0.254mm)" at 4982.22,3334.94 h60
  text "PTH" at 6081.9,3334.94 h60
  text "Round" at 6587.77,3334.94 h60
  text "-" at 7321.57,3334.94 h60
  text "201" at 4382.38,3184.94 h60
  text "12.00mil (0.305mm)" at 4982.22,3184.94 h60
  text "PTH" at 6081.9,3184.94 h60
  text "Round" at 6587.77,3184.94 h60
  text "-" at 7321.57,3184.94 h60
  text "134" at 4382.38,3034.94 h60
  text "16.00mil (0.406mm)" at 4982.22,3034.94 h60
  text "PTH" at 6081.9,3034.94 h60
  text "Round" at 6587.77,3034.94 h60
  text "-" at 7321.57,3034.94 h60
  text "2" at 4382.38,2884.94 h60
  text "20.00mil (0.508mm)" at 4982.22,2884.94 h60
  text "PTH" at 6081.9,2884.94 h60
  text "Round" at 6587.77,2884.94 h60
  text "-" at 7321.57,2884.94 h60
  text "2" at 4382.38,2734.94 h60
  text "31.50mil (0.800mm)" at 4982.22,2734.94 h60
  text "NPTH" at 6081.9,2734.94 h60
  text "Round" at 6587.77,2734.94 h60
  text "-" at 7321.57,2734.94 h60
  text "11" at 4382.38,2584.94 h60
  text "32.00mil (0.813mm)" at 4982.22,2584.94 h60
  text "NPTH" at 6081.9,2584.94 h60
  text "Slot" at 6587.77,2584.94 h60
  text "200.00mil (5.080mm)" at 7321.57,2584.94 h60
  text "B" at 3847.41,2574.95 h66.67
  text "1" at 4382.38,2434.94 h60
  text "32.00mil (0.813mm)" at 4982.22,2434.94 h60
  text "NPTH" at 6081.9,2434.94 h60
  text "Slot" at 6587.77,2434.94 h60
  text "230.00mil (5.842mm)" at 7321.57,2434.94 h60
  text "C" at 3847.41,2424.95 h66.67
  text "3" at 4382.38,2284.94 h60
  text "33.47mil (0.850mm)" at 4982.22,2284.94 h60
  text "PTH" at 6081.9,2284.94 h60
  text "Round" at 6587.77,2284.94 h60
  text "-" at 7321.57,2284.94 h60
  text "74" at 4382.38,2134.94 h60
  text "40.00mil (1.016mm)" at 4982.22,2134.94 h60
  text "PTH" at 6081.9,2134.94 h60
  text "Round" at 6587.77,2134.94 h60
  text "-" at 7321.57,2134.94 h60
  text "20" at 4382.38,1984.94 h60
  text "43.31mil (1.100mm)" at 4982.22,1984.94 h60
  text "PTH" at 6081.9,1984.94 h60
  text "Round" at 6587.77,1984.94 h60
  text "-" at 7321.57,1984.94 h60
  text "2" at 4382.38,1834.94 h60
  text "45.28mil (1.150mm)" at 4982.22,1834.94 h60
  text "PTH" at 6081.9,1834.94 h60
  text "Round" at 6587.77,1834.94 h60
  text "-" at 7321.57,1834.94 h60
  text "A" at 3847.41,1824.95 h66.67
  text "4" at 4382.38,1684.94 h60
  text "47.00mil (1.194mm)" at 4982.22,1684.94 h60
  text "PTH" at 6081.9,1684.94 h60
  text "Round" at 6587.77,1684.94 h60
  text "-" at 7321.57,1684.94 h60
  text "545 Total" at 4382.38,1534.94 h60
  text "Slot definitions :" at 3876.5,1389.97 h60
  text "Routed Path Length" at 4909.19,1389.97 h60
  text "= Calculated from tool start centre position to tool end centre position." at 6011.86,1389.97 h60
  text "Hole Length" at 4909.19,1289.99 h60
  text "= Routed Path Length + Tool Size = Slot length as defined in the PCB layout" at 5601.99,1289.99 h60
  text "Drill Table" at 3835.77,513 h60
  text "FOR 7.874MIL DRILL +0/-7.874MIL" at 3841,377 h60
  text "FOR 8MIL DRILL +0/-8MIL" at 3838,296 h60
  text "FOR 10MIL DRILL +0/-10MIL" at 3837,214 h60
  text "FOR 12MIL DRILL +0/-12MIL" at 3836,129 h60
  text "FOR 16MIL DRILL +0/-16MIL" at 3835.77,40 h60
  text "FOR PTH DRILL +/-3MIL" at 3831.51,-46.55 h60
  text "FOR NPTH DRILL +/-2MIL" at 3835.77,-130 h60
  text ".Layer_Name" at 179.39,-1385.08 h60
M17 Embedded Cavity:
  text ".Layer_Name" at 179.39,-1385.08 h60
M18 Embedded Assembly:
  text ".Layer_Name" at 179.39,-1385.08 h60
M19 Embedded Keepout:
  text ".Layer_Name" at 179.39,-1385.08 h60

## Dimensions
-397.61,-926.58 to 602.39,-926.58 on M2 Board Dimensions
0,0 to 3622.05,0 on M2 Board Dimensions
0,4330.71 to 0,0 on M2 Board Dimensions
